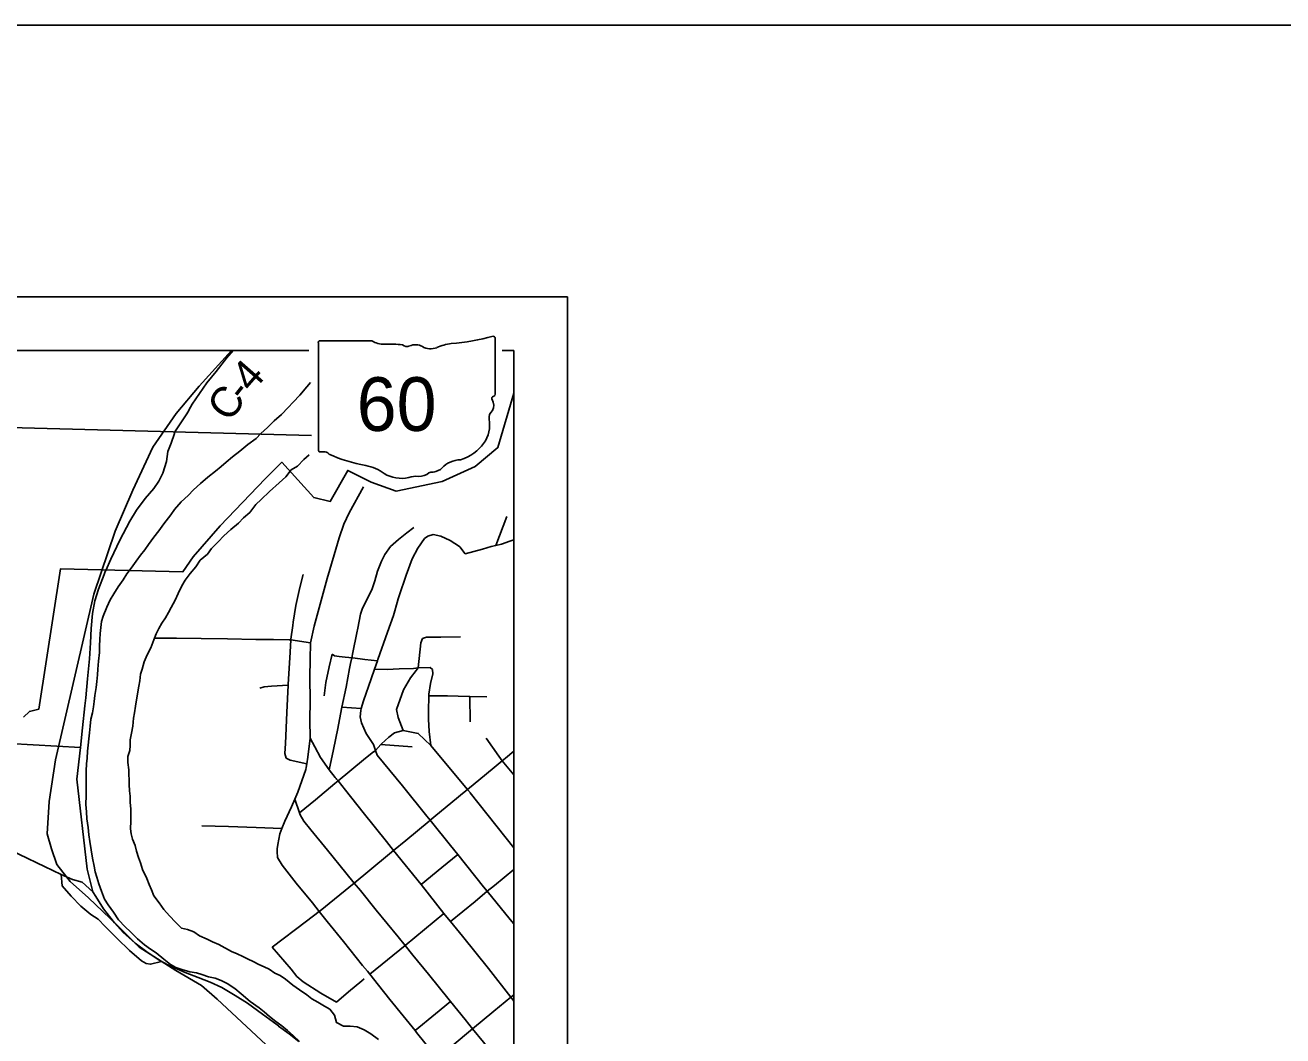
# Model space of a CAD drawing. Extents: x -84548 to 2262448, y -162180 to 525962.
# Drawn here: x 42243 to 54616, y 103579 to 113520 of the extents above; entities that cross this region are included whole.
import ezdxf

# ---------------------------------------------------------------- set-up
doc = ezdxf.new("R2010")
doc.units = 0
for name, color, linetype in [('GM_X_Adjacent_County', 7, 'Continuous'), ('GM_X_County', 7, 'Continuous'), ('GM_X_County_Road', 7, 'Continuous'), ('GM_X_Hydro', 7, 'Continuous'), ('GM_X_Interstate_Location', 7, 'Continuous'), ('GM_X_Major_Lake_Text', 7, 'Continuous'), ('GM_X_Minor_River_Text', 7, 'Continuous'), ('GM_X_Rail_Line', 7, 'Continuous'), ('GM_X_Township_Subdivision_Text', 7, 'Continuous'), ('GM_X_Unincorporated_Location', 7, 'Continuous'), ('GM_X_US_Location', 7, 'Continuous')]:
    doc.layers.add(name, color=color, linetype=linetype)

msp = doc.modelspace()

# ---------------------------------------------------------------- linework, layer by layer
at = {"layer": 'GM_X_Adjacent_County'}
msp.add_lwpolyline([(7920, 113520), (176880, 113520), (176880, 2640), (7920, 2640)], close=True, dxfattribs=at)
at = {"layer": 'GM_X_County'}
for p, q in [((10619, 110849), (47579, 110849)), ((47579, 110849), (47579, 73889)), ((11147, 110321), (45035, 110321)), ((46937, 110321), (47051, 110321)), ((47051, 110321), (47051, 74417))]:
    msp.add_line(p, q, dxfattribs=at)
at = {"layer": 'GM_X_Hydro'}
msp.add_line((41693, 109574), (45060, 109485), dxfattribs=at)
at = {"layer": 'GM_X_Interstate_Location'}
for points in [[(45052, 110006), (45015, 109961), (44946, 109882), (44879, 109811), (44830, 109760), (44765, 109690), (44693, 109627), (44628, 109564), (44561, 109505), (44516, 109454), (44433, 109394), (44354, 109329), (44283, 109273), (44221, 109222), (44170, 109179), (44115, 109134)], [(43718, 107864), (43749, 107931), (43784, 108005), (43819, 108062), (43868, 108127), (43921, 108192), (43966, 108257), (44037, 108316), (44076, 108373), (44143, 108437), (44199, 108496), (44268, 108559), (44341, 108622), (44392, 108673), (44453, 108728), (44514, 108804), (44565, 108855), (44648, 108934), (44743, 109020), (44808, 109077), (44861, 109146), (44921, 109183), (44986, 109247), (45038, 109293)], [(44115, 109134), (44039, 109073), (43968, 109012), (43901, 108948), (43846, 108895), (43779, 108830), (43712, 108755), (43675, 108704), (43608, 108616), (43557, 108545), (43510, 108485), (43457, 108411), (43422, 108361), (43379, 108306), (43335, 108249), (43286, 108180), (43245, 108123), (43208, 108064), (43159, 107995), (43116, 107926), (43081, 107868), (43048, 107795), (43012, 107706), (42994, 107656), (42987, 107595), (42982, 107535), (42979, 107479), (42974, 107415), (42975, 107350), (42964, 107264), (42958, 107186), (42955, 107129), (42950, 107063), (42941, 107005), (42930, 106928), (42923, 106866), (42916, 106814), (42906, 106757), (42891, 106695), (42882, 106625), (42875, 106560), (42858, 106380), (42855, 106311), (42848, 106253), (42845, 106187), (42844, 106111), (42845, 106048), (42844, 105998), (42843, 105944), (42841, 105854), (42846, 105782), (42851, 105713), (42862, 105627), (42871, 105557), (42878, 105491), (42892, 105407), (42907, 105327), (42922, 105249), (42933, 105193), (42948, 105139), (42967, 105073), (42994, 105002), (43025, 104924), (43060, 104868), (43114, 104795), (43163, 104719), (43226, 104650), (43279, 104603), (43348, 104534), (43417, 104475), (43478, 104432), (43532, 104396), (43607, 104333), (43674, 104280), (43727, 104251), (43785, 104230), (43862, 104209), (43928, 104198), (43982, 104181), (44047, 104160), (44111, 104145), (44173, 104124), (44230, 104095), (44305, 104046), (44368, 103993), (44457, 103916), (44544, 103853), (44595, 103814), (44648, 103770), (44710, 103721), (44769, 103676), (44824, 103631), (44879, 103582), (44942, 103522)], [(45720, 103543), (45645, 103600), (45577, 103637), (45510, 103666), (45440, 103675), (45374, 103674), (45307, 103709), (45288, 103781), (45241, 103840), (45187, 103871), (45122, 103910), (45065, 103942), (45013, 103981), (44942, 104032), (44877, 104079), (44804, 104136), (44751, 104171), (44701, 104197), (44644, 104234), (44594, 104259), (44543, 104280), (44487, 104311), (44436, 104333), (44384, 104358), (44329, 104385), (44273, 104410), (44148, 104476), (44085, 104504), (44035, 104529), (43958, 104564), (43902, 104601), (43841, 104624), (43783, 104639), (43722, 104698), (43663, 104760), (43608, 104823), (43561, 104888), (43509, 104956), (43485, 105015), (43464, 105067), (43441, 105127), (43399, 105215), (43378, 105281), (43359, 105332), (43340, 105396), (43325, 105452), (43300, 105514), (43286, 105566), (43281, 105616), (43282, 105690), (43283, 105758), (43282, 105813), (43277, 105875), (43276, 105935), (43269, 105989), (43266, 106051), (43264, 106194), (43253, 106266), (43254, 106328), (43273, 106386), (43276, 106436), (43277, 106489), (43288, 106555), (43301, 106625), (43308, 106704), (43319, 106756), (43330, 106823), (43344, 106923), (43361, 107020), (43370, 107070), (43379, 107136), (43394, 107187), (43415, 107257), (43444, 107328), (43479, 107397), (43510, 107475), (43531, 107534), (43560, 107585), (43587, 107639), (43623, 107690), (43654, 107743), (43679, 107793), (43718, 107864)]]:
    msp.add_lwpolyline(points, dxfattribs=at)
at = {"layer": 'GM_X_Major_Lake_Text'}
msp.add_line((47020, 103959), (47051, 103921), dxfattribs=at)
for points in [[(45293, 106120), (45233, 106196), (45150, 106316), (45093, 106422), (45048, 106506), (45043, 106686), (45047, 106874), (45044, 107107), (45046, 107281), (45051, 107446), (45086, 107610), (45146, 107825), (45214, 108079), (45282, 108310), (45333, 108479), (45378, 108612), (45431, 108724), (45573, 108979)], [(46424, 104708), (46363, 104783), (46138, 105066), (45868, 105403), (45799, 105490), (45570, 105775), (45396, 105994), (45321, 106086), (45305, 106105), (45302, 106109), (45293, 106120)], [(47020, 103959), (46801, 104242), (46545, 104560), (46428, 104703), (46424, 104708)], [(45625, 102805), (45671, 102842), (45699, 102865), (45868, 103003), (46041, 103144), (46248, 103314), (46297, 103356), (46445, 103482), (46643, 103647), (46855, 103822), (47020, 103959)]]:
    msp.add_lwpolyline(points, dxfattribs=at)
at = {"layer": 'GM_X_Minor_River_Text'}
for points in [[(43854, 109733), (43887, 109792), (43957, 109896), (44031, 110001), (44121, 110113), (44224, 110246), (44289, 110321)], [(43711, 109503), (43717, 109521), (43833, 109697), (43852, 109730), (43854, 109733)], [(43037, 108157), (43086, 108266), (43176, 108455), (43274, 108641), (43339, 108751), (43425, 108863), (43509, 108961), (43557, 109034), (43598, 109115), (43633, 109228), (43647, 109328), (43679, 109408), (43711, 109503)]]:
    msp.add_lwpolyline(points, dxfattribs=at)
at = {"layer": 'GM_X_Rail_Line'}
for p, q in [((45128, 110397), (45128, 109341)), ((45128, 109341), (45128, 110397)), ((45128, 109341), (45128, 110397)), ((45145, 110416), (45654, 110416)), ((46868, 110442), (46868, 109889)), ((46868, 109889), (46868, 109889))]:
    msp.add_line(p, q, dxfattribs=at)
for centre, major_axis, start_param, end_param in [((45147, 110400), (20.2, 0), 1.712693, 3.28349), ((45776, 110538), (196, 0), 4.042523, 4.731795), ((45840, 109822), (702, 0), 1.404758, 1.657858), ((46000, 110405), (56.4, 0), 3.836095, 5.185415), ((46083, 110283), (117, 0), 0.950623, 2.079405), ((46483, 110093), (371, 0), 1.699011, 2.107814), ((46248, 111856), (1845, 0), 4.814394, 5.042369), ((46848, 110444), (19.4, 0), 6.141152, 7.989035), ((46234, 110450), (141, 0), 4.081561, 5.145723), ((46863, 109848), (30, 0), 1.883978, 3.671073), ((46847, 109887), (20.7, 0), 5.05454, 6.418171), ((46673, 109779), (180, 0), 5.934695, 6.695948), ((46351, 109587), (462, 0), 5.101752, 6.440018), ((46937, 109658), (131, 0), 2.387724, 3.262537), ((45148, 109338), (20.3, 0), 3.00124, 4.508301), ((45151, 109446), (155, 0), 4.665946, 4.897461), ((45182, 109280), (56, 0), 0.519207, 1.627899), ((45889, 110229), (1333, 0), 4.195997, 4.488961), ((45492, 108866), (417, 0), 0.823519, 1.323587), ((46242, 109093), (39.7, 0), 1.147584, 2.315152), ((46226, 109238), (149, 0), 4.937069, 5.64225), ((46546, 109044), (253, 0), 1.647645, 2.488434), ((45943, 109274), (265, 0), 4.026481, 4.996735), ((46096, 108909), (217, 0), 1.495662, 1.94098), ((46115, 109195), (141, 0), 4.691044, 5.507374)]:
    msp.add_ellipse(centre, major_axis=major_axis, ratio=0.8, start_param=start_param, end_param=end_param, dxfattribs=at)
at = {"layer": 'GM_X_Township_Subdivision_Text'}
msp.add_lwpolyline([(47051, 98634), (47051, 109899), (46894, 109365), (46670, 109180), (46345, 109030), (45894, 108938), (45647, 109025), (45417, 109140), (45245, 108836), (45082, 108873), (44769, 109221), (44606, 109058), (44161, 108597), (43896, 108292), (43796, 108144), (42591, 108171), (42377, 106791), (42285, 106770), (42228, 106712)], dxfattribs=at)
at = {"layer": 'GM_X_Unincorporated_Location'}
msp.add_lwpolyline([(44999, 103132), (44133, 103939), (43977, 104073), (43724, 104221), (43366, 104450), (43149, 104668), (42867, 104937), (42686, 105098), (42556, 105264), (42501, 105418), (42461, 105566), (42479, 105883), (42541, 106295), (42920, 107922), (43130, 108543), (43303, 108947), (43500, 109369), (43729, 109701), (43956, 109969), (44274, 110321)], dxfattribs=at)
at = {"layer": 'GM_X_US_Location'}
msp.add_line((47020, 103959), (47051, 103984), dxfattribs=at)
for points in [[(46875, 108403), (46982, 108687)], [(45562, 107787), (45562, 107787), (45601, 107862), (45658, 107977), (45683, 108055), (45711, 108150), (45748, 108248), (45783, 108313), (45838, 108391), (45916, 108460), (45999, 108527), (46068, 108578)], [(45911, 107865), (45911, 107866), (45923, 107908), (45990, 108109), (46050, 108270), (46105, 108377), (46172, 108472), (46206, 108494), (46256, 108509), (46332, 108495), (46426, 108452), (46515, 108393), (46518, 108390)], [(46518, 108390), (46572, 108321), (46742, 108365)], [(46742, 108365), (46827, 108393), (46875, 108403), (46930, 108416), (47012, 108443), (47051, 108458)], [(42832, 106824), (42841, 106905), (42857, 107090), (42877, 107288), (42885, 107443), (42894, 107587), (42907, 107734), (42928, 107858), (42964, 107971), (43019, 108117), (43032, 108147), (43037, 108157)], [(44877, 107615), (44881, 107647), (44906, 107811), (44944, 107990), (44979, 108116)], [(45515, 107590), (45541, 107725), (45562, 107787)], [(45691, 106387), (45670, 106443), (45599, 106554), (45552, 106658), (45539, 106716), (45545, 106780), (45550, 106798), (45572, 106873), (45648, 107092), (45681, 107187), (45709, 107267), (45714, 107281), (45807, 107548), (45867, 107715), (45911, 107865)], [(44812, 106311), (44798, 106357), (44803, 106456), (44818, 106758), (44831, 107029), (44831, 107035), (44850, 107354), (44856, 107474), (44857, 107482), (44876, 107614), (44877, 107615)], [(45444, 107241), (45444, 107242), (45456, 107298), (45466, 107348), (45506, 107544), (45515, 107590), (45515, 107590)], [(43508, 107489), (43732, 107489), (43974, 107488), (44233, 107484), (44513, 107479), (44687, 107478), (44839, 107474), (44840, 107474)], [(44840, 107474), (44856, 107474), (45051, 107446)], [(46091, 107173), (46110, 107198), (46110, 107198), (46137, 107444), (46151, 107488)], [(46151, 107488), (46191, 107499), (46333, 107500), (46525, 107504)], [(45184, 106922), (45202, 107053), (45233, 107208), (45262, 107334)], [(45262, 107334), (45285, 107318), (45333, 107310), (45391, 107303), (45426, 107300), (45427, 107300)], [(45427, 107300), (45456, 107298), (45467, 107298), (45585, 107281), (45709, 107267)], [(45233, 106196), (45276, 106396), (45320, 106603), (45356, 106796), (45359, 106813), (45400, 107008), (45434, 107191), (45444, 107241)], [(45681, 107187), (45804, 107183), (45924, 107188), (46064, 107193), (46110, 107198), (46228, 107201), (46252, 107181)], [(45962, 106583), (45914, 106710), (45898, 106790), (45964, 106981), (46035, 107101), (46091, 107172), (46091, 107173)], [(46213, 106863), (46214, 106922), (46215, 106940), (46230, 107046), (46253, 107141), (46252, 107181)], [(41039, 107056), (41030, 106985), (41008, 106883), (41004, 106650), (41003, 106554), (41021, 106518), (41054, 106494), (41579, 106468), (42090, 106453), (42787, 106414)], [(44552, 106998), (44593, 107013), (44667, 107019), (44831, 107029)], [(46214, 106922), (46397, 106922), (46607, 106916), (46619, 106916), (46785, 106913)], [(46622, 106669), (46619, 106916)], [(42808, 106609), (42832, 106824)], [(45359, 106813), (45550, 106798)], [(46234, 106435), (46218, 106573), (46211, 106694), (46212, 106834), (46213, 106862), (46213, 106863)], [(44737, 103675), (44736, 103676), (44723, 103686), (44577, 103791), (44432, 103902), (44309, 103975), (44177, 104055), (44062, 104108), (43945, 104152), (43818, 104201), (43666, 104266), (43583, 104310), (43561, 104322), (43439, 104406), (43327, 104489), (43209, 104597), (43121, 104691), (43014, 104829), (42939, 104948), (42910, 104995), (42855, 105217), (42752, 106105), (42787, 106414), (42808, 106609)], [(45672, 106372), (45691, 106387), (45743, 106443), (45749, 106451), (45821, 106517), (45876, 106560), (45962, 106583)], [(46620, 105971), (46595, 106003), (46593, 106005), (46234, 106435), (46111, 106553), (45962, 106583)], [(45007, 106219), (45013, 106253), (45024, 106321), (45048, 106506)], [(45743, 106443), (46050, 106423)], [(46904, 106329), (46903, 106330), (46777, 106507)], [(44812, 106311), (44849, 106290), (45013, 106253)], [(45306, 106074), (45307, 106075), (45321, 106086), (45436, 106181), (45591, 106309), (45671, 106371), (45672, 106372)], [(46241, 105685), (46229, 105700), (46196, 105740), (45955, 106039), (45707, 106341), (45691, 106387)], [(46857, 106218), (46857, 106218), (46937, 106283), (46969, 106310), (47051, 106379)], [(47051, 106145), (46937, 106283), (46904, 106329)], [(44895, 105908), (44925, 105976), (44964, 106087), (45003, 106199), (45007, 106219)], [(46488, 105915), (46525, 105945), (46595, 106003), (46783, 106156), (46857, 106218)], [(44941, 105773), (45099, 105899), (45291, 106061), (45306, 106074)], [(45012, 104707), (45137, 104802), (45146, 104808), (45481, 105082), (45808, 105353), (45868, 105403), (45987, 105501), (46219, 105692), (46229, 105700), (46488, 105915), (46488, 105915)], [(47051, 105429), (46622, 105969), (46620, 105971)], [(44727, 105336), (44721, 105390), (44724, 105417), (44728, 105460), (44750, 105566), (44769, 105618), (44797, 105691), (44862, 105833), (44895, 105908)], [(47051, 103157), (46884, 103358), (46826, 103428), (46753, 103517), (46643, 103647), (46572, 103739), (46428, 103916), (46414, 103934), (46210, 104187), (46057, 104374), (45981, 104469), (45913, 104554), (45697, 104815), (45542, 105008), (45481, 105082), (45399, 105182), (45219, 105405), (45054, 105604), (44985, 105692), (44948, 105752), (44941, 105773), (44895, 105908)], [(41577, 105687), (41622, 105666), (41722, 105600), (42024, 105440), (42598, 105166), (42708, 105116), (42804, 105090), (42910, 104995)], [(47051, 104680), (47015, 104724), (46790, 105001), (46753, 105046), (46499, 105362), (46429, 105450), (46242, 105683), (46241, 105685)], [(43983, 105644), (44245, 105637), (44517, 105629), (44769, 105618)], [(45610, 104214), (45563, 104271), (45376, 104506), (45214, 104704), (45137, 104802), (45071, 104887), (44909, 105082), (44772, 105258), (44727, 105332), (44727, 105336)], [(46138, 105066), (46342, 105234), (46499, 105362)], [(46428, 104703), (46669, 104901), (46790, 105001), (46860, 105059), (47051, 105215)], [(42598, 105166), (42606, 105054), (42695, 104953), (42792, 104853), (42889, 104774), (42961, 104725), (43030, 104655), (43147, 104538), (43271, 104419), (43388, 104316), (43434, 104291), (43476, 104283), (43583, 104310)], [(44673, 104452), (45011, 104706), (45012, 104707)], [(45634, 104185), (45981, 104469), (46363, 104783)], [(45307, 103910), (45152, 103998), (44978, 104109), (44916, 104162), (44861, 104236), (44673, 104452)], [(46297, 103356), (46256, 103408), (46094, 103613), (46079, 103632), (45961, 103777), (45830, 103938), (45721, 104078), (45634, 104185), (45610, 104214)], [(45307, 103910), (45424, 104013), (45557, 104121), (45580, 104140)], [(46079, 103632), (46280, 103797), (46428, 103916)], [(44935, 103524), (44839, 103600), (44737, 103675)]]:
    msp.add_lwpolyline(points, dxfattribs=at)

# ---------------------------------------------------------------- texts
at = {"layer": 'GM_X_County_Road'}
for s, rotation, p in [('4', 48.843, (44472, 109895)), ('C', 53.9644, (44255, 109604)), ('-', 51.6268, (44398, 109801))]:
    msp.add_text(s, height=300, rotation=rotation, dxfattribs=at).set_placement(p)
at = {"layer": 'GM_X_Rail_Line'}
msp.add_text('60', height=528, dxfattribs=at).set_placement((45505, 109529))

doc.saveas('drawing.dxf')
